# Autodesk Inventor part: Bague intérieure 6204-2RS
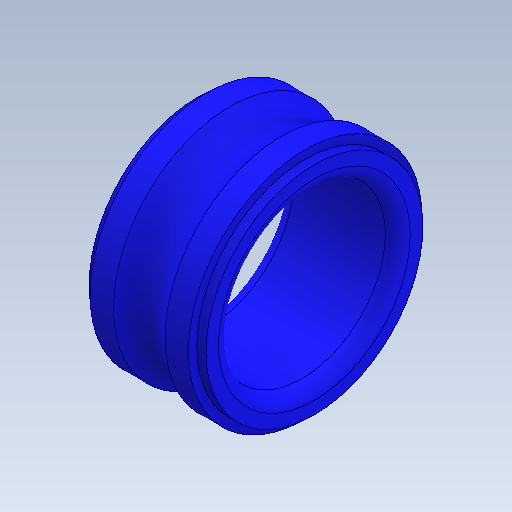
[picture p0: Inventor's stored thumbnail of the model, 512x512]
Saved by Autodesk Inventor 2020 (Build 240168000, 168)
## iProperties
Created: 2003-06
Part Number: Bague intérieure 6204-2RS
Material: Générique
Document SubType Name: Modeling
Designer: Bruno
Density: 1 g/cm^3
Appearance: Par défaut
Author: Bruno
Sending System: SolidWorks 2011
Last Author: frederic
Last Saved: 2012-02-20
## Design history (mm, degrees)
feature "Base-Révolution"
node "Solide1"
